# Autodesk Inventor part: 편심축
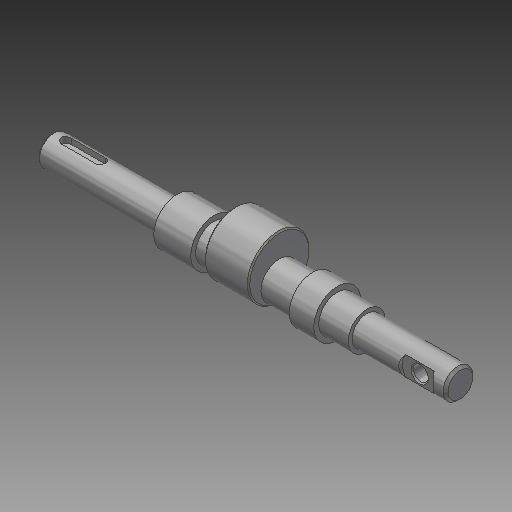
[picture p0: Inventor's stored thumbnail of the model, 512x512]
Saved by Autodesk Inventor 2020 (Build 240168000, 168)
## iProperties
Created: 2015-12
Part Number: 편심축
Document SubType Name: Modeling
Designer: mdu
Density: 7.86 g/cm^3
Mass: 245.857 g
Surface Area: 93.8652 cm^2
Volume: 31.2795 cm^3
Material: 강철, 연강
Appearance: 강철
Company: 한국ATC센터
Author: mdu
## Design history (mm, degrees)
sketch "스케치1"
  geometry: L1 (-83, 0)-(83, 0); L2 (-83, 0)-(-83, 6); L3 (-83, 6)-(-32, 6); L4 (-32, 6)-(-32, 9.5); L5 (-32, 9.5)-(-17, 9.5); L6 (-17, 9.5)-(-17, 7.5); L7 (-17, 7.5)-(45, 7.5); L8 (83, 6)-(83, 0); L9 (33, 7.5)-(33, 9.5); L10 (33, 9.5)-(23, 9.5); L11 (23, 9.5)-(23, 7.5); L12 (45, 7.5)-(45, 6); L13 (45, 6)-(83, 6); 2 further points
  constraints: 26 end point, 6 parallel, 6 perpendicular, 2 point on line, 1 coincident, 1 horizontal, 1 midpoint
  dimensions: "d1" = 12 diameter of L3 L1; "d2" = 15 diameter of L7 L1; "d4" = 15 distance of L4.end L5.end; "d5" = 19 diameter of L5 L1; "d24" = 10 distance of L9.end L10.end; "d25" = 19 diameter of L10 L1; "d27" = 40 distance between parallel lines of L11 L6; "d28" = 51 distance of L2.end L3.end; "d29" = 50 distance between parallel lines of L8 L9; "d41" = 38 distance between parallel lines of L8 L12; "d42" = 12 diameter of L13 L1
revolve "회전1" stored, may be unused: angle "d6" = 90 deg
node "작업 평면1"
sketch "스케치2"
  geometry: C1 r 7.5 at (0, 0) reference; C2 r 12.5 at (0, 4.5); 1 further point
  constraints: 1 centre point, 1 vertical alignment
  dimensions: "d8" = 4.5 distance of point (0, 0) C2.centre; "d9" = 25 diameter of C2
extrude "돌출1" join sketch "스케치2" distance "d10" = 18; taper "d11" = 0 deg
chamfer "모따기1" distance "d12" = 1; stored, may be unused: second distance "d13" = 2, angle "d14" = 45 deg
chamfer "모따기2" distance "d15" = 0.5; stored, may be unused: second distance "d16" = 2, angle "d17" = 45 deg
node "작업 평면2"
sketch "스케치3"
  geometry: L1 (5.5, -2)-(19.5, -2); L2 (19.5, 2)-(5.5, 2); L3 (25.5, 5)-(25.5, -5) reference; A1 r 2 centre (19.5, 0) between (19.5, -2) and (19.5, 2); A2 r 2 centre (5.5, 0) between (5.5, 2) and (5.5, -2); 2 further points
  constraints: 4 end point, 4 point on circle, 4 tangent, 2 centre point, 1 horizontal, 1 horizontal alignment, 1 midpoint, 1 parallel
  dimensions: "d18" = 4 distance edge to line of A1 L3; "d19" = 4 distance between parallel lines of L2 L1; "d20" = 18 dimension on A1 A2
extrude "돌출2" cut sketch "스케치3" distance "d21" = 2.5; taper "d22" = 0 deg
revolve "회전2" stored, may be unused: angle "d26" = 90 deg
node "작업 평면3"
sketch "스케치4"
  geometry: L1 (44, 5)-(44, -5) reference; 2 further points
  constraints: 1 horizontal alignment
  dimensions: "d30" = 12 distance from line of point (32, 0) L1
hole "구멍1" sketch "스케치4" at (32, 0) diameter "d31" = 6; stored, may be unused: countersink angle "d35" = 90 deg, drill point angle "d37" = 118 deg; dims "d32" = 6, "d33" = 14, "d34" = 3, "d36" = 8
node "작업 평면4"
sketch "스케치5"
  geometry: C1 r 3 at (32, 0) reference; C2 r 8 at (32, 0); 2 further points
  constraints: 1 centre point, 1 coincident, 1 other
  dimensions: "d38" = 16 diameter of C2
extrude "돌출3" cut sketch "스케치5" distance "d39" = 3; taper "d40" = 0 deg
sketch "스케치6"
  geometry: L1 (-82, -6)-(-32, -6) reference; L2 (-83, -5)-(-83, 5) reference; L3 (-82, 6)-(-32, 6) reference; L4 (-63, 6)-(-63, -6); L5 (-63, -6)-(-61.5, -6); L6 (-63, -4.5)-(-61.5, -6); L7 (-63, -6)-(-63, -4.5); 2 further points
  constraints: 8 end point, 4 point on line, 2 perpendicular, 1 coincident
  dimensions: "d43" = 20 distance between parallel lines of L4 L2; "d44" = 45 deg angle of L6 L7; "d45" = 3 diameter of L5.end L4
revolve "회전3" stored, may be unused: angle "d46" = 90 deg
node "작업점1"
chamfer "모따기3" distance "d47" = 0.5; stored, may be unused: second distance "d48" = 2, angle "d49" = 45 deg
node "솔리드1"
node "투영된 루프1"
other parameters: "d7" = 8.5
